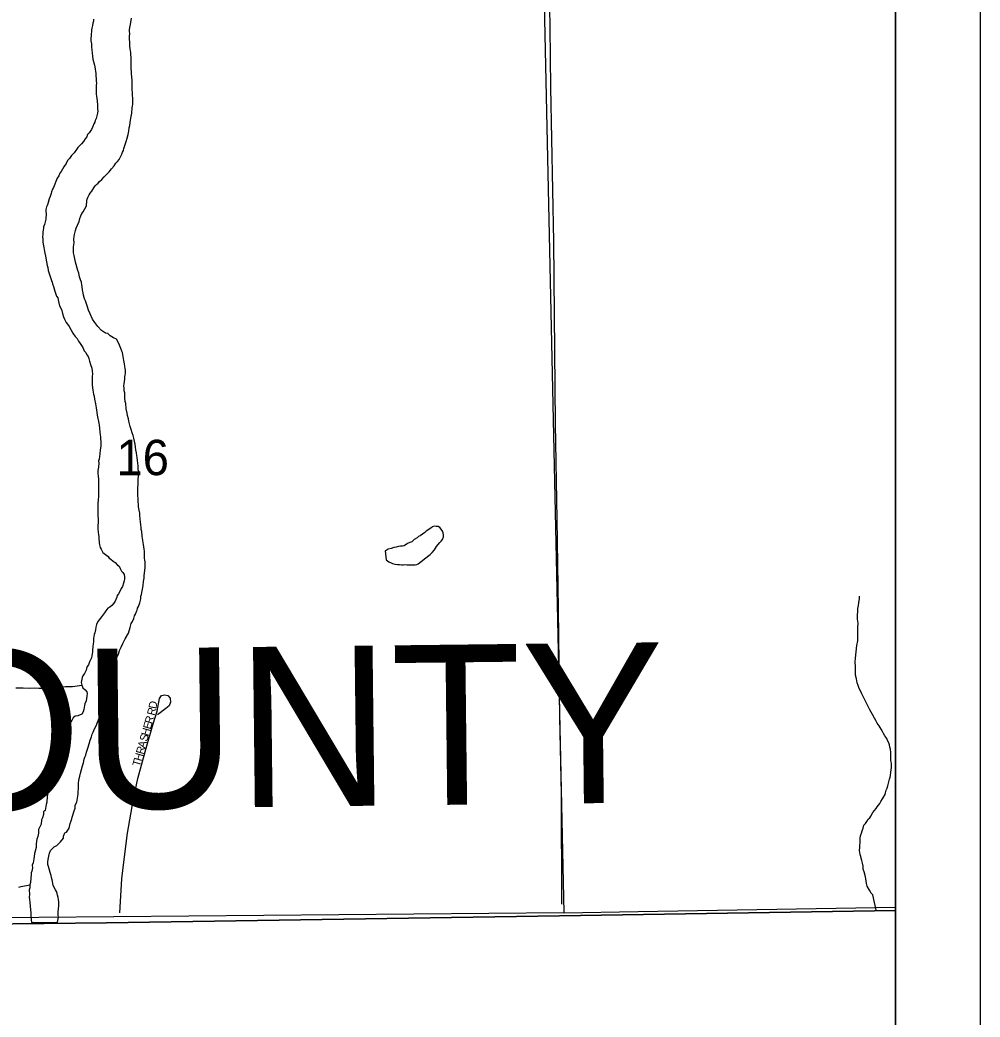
# Model space of a CAD drawing. Extents: x -10.1 to 68, y -9.5 to 29.2.
# Drawn here: x 7.864 to 9, y 16.77 to 17.95 of the extents above; entities that cross this region are included whole.
import ezdxf

# ---------------------------------------------------------------- set-up
doc = ezdxf.new("R2010")
doc.units = 0
for name, color, linetype in [('GM_X_Adjacent_County', 7, 'Continuous'), ('GM_X_Adjacent_County_Text', 7, 'Continuous'), ('GM_X_Major_River', 7, 'Continuous'), ('GM_X_Minor_Lake', 7, 'Continuous'), ('GM_X_Minor_River', 7, 'Continuous'), ('GM_X_Section', 7, 'Continuous'), ('GM_X_Section_Text', 7, 'Continuous'), ('GM_X_Township', 7, 'Continuous'), ('GM_X_Township_Road', 7, 'Continuous'), ('GM_X_Township_Subdivision', 7, 'Continuous'), ('GM_X_Township_Subdivision_Text', 7, 'Continuous'), ('SH_Data', 7, 'Continuous')]:
    doc.layers.add(name, color=color, linetype=linetype)

msp = doc.modelspace()

# ---------------------------------------------------------------- linework, layer by layer
at = {"layer": 'GM_X_Adjacent_County'}
for points in [[(2.1, 16.7954), (2.1, 14.1), (8.9, 14.1), (8.9, 16.8967)], [(8.9, 16.8967), (8.5023, 16.8904), (7.9665, 16.8821), (7.5233, 16.8774), (6.5083, 16.8667), (6.2435, 16.8638), (4.8206, 16.8372), (4.1632, 16.8285), (3.6875, 16.8223), (2.8045, 16.808), (2.1, 16.7954)]]:
    msp.add_lwpolyline(points, dxfattribs=at)
at = {"layer": 'GM_X_Major_River'}
msp.add_line((7.8774, 16.8822), (7.9083, 16.8826), dxfattribs=at)
for points in [[(7.9511, 17.951), (7.9508, 17.9484), (7.9501, 17.9461), (7.9498, 17.9434), (7.9491, 17.9403), (7.9484, 17.9384), (7.9484, 17.9358), (7.9481, 17.9335), (7.9482, 17.9316), (7.9479, 17.9281), (7.9479, 17.9251), (7.9484, 17.9217), (7.9485, 17.9182), (7.9489, 17.9141), (7.9494, 17.911), (7.9499, 17.9072), (7.9503, 17.9035), (7.952, 17.8966), (7.9524, 17.8947), (7.9529, 17.8917), (7.9533, 17.8894), (7.9537, 17.8868), (7.9538, 17.8837), (7.9543, 17.8803), (7.954, 17.8777), (7.9544, 17.8754), (7.9541, 17.8723), (7.9541, 17.8693), (7.9542, 17.8662), (7.9543, 17.8624), (7.9547, 17.8598), (7.9548, 17.8571), (7.9552, 17.8545), (7.9553, 17.8526), (7.9557, 17.8507), (7.9558, 17.8476), (7.9558, 17.8446), (7.9559, 17.8423), (7.9556, 17.8396), (7.9549, 17.8366), (7.9542, 17.8335), (7.9531, 17.8312), (7.9524, 17.8289), (7.9513, 17.827), (7.9502, 17.8239), (7.9484, 17.8205), (7.9458, 17.8166), (7.944, 17.8143), (7.9429, 17.8116), (7.9411, 17.8093), (7.9392, 17.8062), (7.9366, 17.8034), (7.9344, 17.8011), (7.9325, 17.7992), (7.9307, 17.7968), (7.9281, 17.793), (7.9248, 17.7895), (7.9226, 17.786), (7.92, 17.7837), (7.9185, 17.7802), (7.9159, 17.7763), (7.9141, 17.7733), (7.9126, 17.7709), (7.9112, 17.7686), (7.9101, 17.7656)], [(7.937, 17.7209), (7.9388, 17.7232), (7.9425, 17.7301), (7.9431, 17.7359), (7.9435, 17.7378), (7.9442, 17.7401), (7.946, 17.7432), (7.9471, 17.7451), (7.9489, 17.7474), (7.9515, 17.7513), (7.953, 17.7536), (7.9545, 17.7555), (7.9563, 17.7571), (7.9582, 17.759), (7.9608, 17.7614), (7.9634, 17.7645), (7.966, 17.7668), (7.9693, 17.7703), (7.9723, 17.7738), (7.9753, 17.7773), (7.9775, 17.7804), (7.9793, 17.7827), (7.9812, 17.785), (7.983, 17.7881), (7.9845, 17.7912), (7.9852, 17.7935), (7.9863, 17.7954), (7.987, 17.7981), (7.9895, 17.8062), (7.9909, 17.81), (7.9919, 17.8146), (7.9926, 17.8184), (7.9933, 17.8222), (7.994, 17.8253), (7.9943, 17.8287), (7.9953, 17.8337), (7.9963, 17.8398), (7.9969, 17.8459), (7.9972, 17.8482), (7.9976, 17.8505), (7.9975, 17.8539), (7.9974, 17.8558), (7.9974, 17.8577), (7.9973, 17.8604), (7.9973, 17.8638), (7.9968, 17.8676), (7.9967, 17.8706), (7.9966, 17.8748), (7.9966, 17.8782), (7.9965, 17.8828), (7.996, 17.8862), (7.9959, 17.8893), (7.9955, 17.8912), (7.9954, 17.8934), (7.9954, 17.8961), (7.9957, 17.8999), (7.9956, 17.9026), (7.9955, 17.9056), (7.9951, 17.909), (7.995, 17.9117), (7.9946, 17.9136), (7.9942, 17.9159), (7.9941, 17.9193), (7.994, 17.9235), (7.9935, 17.9276), (7.9935, 17.9303), (7.9938, 17.9341), (7.9937, 17.9364), (7.9937, 17.9383), (7.994, 17.941), (7.9947, 17.9448), (7.996, 17.9521)], [(7.9101, 17.7656), (7.9079, 17.7628), (7.9036, 17.7517), (7.9025, 17.7498), (7.9014, 17.7467), (7.9007, 17.7448), (7.8996, 17.741), (7.8985, 17.7383), (7.8975, 17.7341), (7.8964, 17.7314), (7.8953, 17.7291), (7.8946, 17.7256), (7.8947, 17.723), (7.8948, 17.7211), (7.8945, 17.7142), (7.8928, 17.7081), (7.8917, 17.7054), (7.8917, 17.7035), (7.8914, 17.7012), (7.8911, 17.6993), (7.8911, 17.6966), (7.8908, 17.6936), (7.8909, 17.6905), (7.891, 17.6875), (7.8914, 17.6848), (7.8922, 17.681), (7.8931, 17.6761), (7.8935, 17.6742), (7.894, 17.6704), (7.8953, 17.664), (7.8962, 17.6594), (7.897, 17.6572), (7.8974, 17.6538), (7.9011, 17.6417), (7.9019, 17.6398), (7.9024, 17.6379), (7.9036, 17.6345), (7.9052, 17.6292), (7.9073, 17.6232), (7.9088, 17.6213), (7.9097, 17.6171), (7.9109, 17.6118), (7.9126, 17.6081), (7.9134, 17.6062), (7.9142, 17.6028), (7.9154, 17.599), (7.9166, 17.596), (7.9186, 17.5922), (7.9202, 17.59), (7.9222, 17.5874), (7.9241, 17.584), (7.9265, 17.5795), (7.9293, 17.5757), (7.9316, 17.5731), (7.9332, 17.5701), (7.9352, 17.5671), (7.9383, 17.5626), (7.9399, 17.5585), (7.9419, 17.5566), (7.9431, 17.554), (7.9447, 17.5517), (7.9455, 17.5495), (7.9463, 17.5464), (7.9475, 17.5423), (7.9488, 17.5381), (7.9492, 17.5347), (7.9497, 17.5313), (7.9494, 17.5282), (7.9494, 17.526), (7.9495, 17.5229), (7.9492, 17.518), (7.9501, 17.5119), (7.951, 17.5073), (7.9518, 17.5051), (7.9523, 17.5013), (7.9532, 17.496), (7.954, 17.4911), (7.9549, 17.4861), (7.9554, 17.4823), (7.9571, 17.4729), (7.9576, 17.4706), (7.958, 17.4672), (7.9585, 17.4622), (7.959, 17.4592), (7.9594, 17.4569), (7.9594, 17.4543), (7.9595, 17.4508), (7.9596, 17.4459), (7.959, 17.4413), (7.9583, 17.4367), (7.9577, 17.4303), (7.957, 17.4283), (7.9571, 17.4257), (7.9568, 17.4211), (7.9561, 17.4169), (7.9562, 17.4135), (7.9566, 17.4104), (7.9567, 17.4066), (7.9568, 17.4032), (7.9569, 17.3998), (7.957, 17.3948)], [(8.0051, 17.3701), (8.0043, 17.3742), (8.0042, 17.3769), (8.0038, 17.3799), (8.0037, 17.383), (8.0036, 17.3879), (8.0035, 17.3906), (8.0035, 17.3929), (8.0034, 17.3974), (8.0037, 17.4001), (8.004, 17.4035), (8.0039, 17.4073), (8.0042, 17.41), (8.0045, 17.4157), (8.004, 17.418), (8.004, 17.4203), (8.0039, 17.4226), (8.0035, 17.4256), (8.003, 17.429), (8.0026, 17.4324), (8.0021, 17.4347), (8.002, 17.4381), (8.0012, 17.4415), (8.0008, 17.4446), (8.0003, 17.4483), (7.9995, 17.4517), (7.9986, 17.4552), (7.9978, 17.4586), (7.9966, 17.4616), (7.9957, 17.4657), (7.9945, 17.4691), (7.9937, 17.4722), (7.9928, 17.4752), (7.9924, 17.4782), (7.9912, 17.482), (7.9907, 17.485), (7.9898, 17.49), (7.9893, 17.4964), (7.9885, 17.4987), (7.988, 17.5029), (7.9879, 17.5089), (7.9874, 17.5112), (7.9874, 17.5146), (7.9869, 17.5173), (7.9873, 17.5196), (7.9879, 17.5249), (7.9882, 17.528), (7.9885, 17.5299), (7.9889, 17.5322), (7.9888, 17.5356), (7.9884, 17.5375), (7.9879, 17.5401), (7.9875, 17.5432), (7.9874, 17.5451), (7.987, 17.547), (7.9853, 17.5565), (7.9845, 17.5583), (7.9833, 17.5614), (7.9816, 17.5651), (7.9796, 17.5696), (7.9781, 17.5723), (7.9746, 17.5741), (7.9707, 17.5763), (7.968, 17.5789), (7.9653, 17.5796), (7.9603, 17.5825), (7.956, 17.5874), (7.9525, 17.5922), (7.9497, 17.596), (7.9469, 17.6024), (7.9449, 17.6065), (7.9433, 17.6118), (7.9416, 17.6179), (7.9404, 17.6201), (7.9392, 17.6243), (7.9387, 17.6273), (7.9379, 17.6303), (7.9374, 17.6345), (7.937, 17.6368), (7.9366, 17.6398), (7.9357, 17.6425), (7.9345, 17.6462), (7.9337, 17.6504), (7.9324, 17.6538), (7.9295, 17.6636), (7.9287, 17.6674), (7.9279, 17.6712), (7.9274, 17.6746), (7.9273, 17.6788), (7.9272, 17.6815), (7.9279, 17.6864), (7.9278, 17.6906), (7.9281, 17.6937), (7.9284, 17.6963), (7.9295, 17.7009), (7.9305, 17.7036), (7.932, 17.7071), (7.9338, 17.7117), (7.9348, 17.7151), (7.9359, 17.7182), (7.937, 17.7209)], [(7.957, 17.3948), (7.9567, 17.3903), (7.9568, 17.3865), (7.9565, 17.3819), (7.9562, 17.3785), (7.956, 17.3739), (7.956, 17.3705), (7.9561, 17.3678), (7.9562, 17.364), (7.9563, 17.3591), (7.9564, 17.3549), (7.9561, 17.3526), (7.9562, 17.348), (7.9563, 17.3442), (7.9567, 17.3408), (7.9571, 17.3389), (7.9572, 17.337), (7.9577, 17.3317), (7.9581, 17.329), (7.959, 17.326), (7.9601, 17.3238), (7.9621, 17.32), (7.9683, 17.3152), (7.9695, 17.3133), (7.9714, 17.3122), (7.9742, 17.3096), (7.9765, 17.3082), (7.9792, 17.3052), (7.9815, 17.3037), (7.9824, 17.3011), (7.9839, 17.2981), (7.9855, 17.2962), (7.9871, 17.2939), (7.9875, 17.2913), (7.9876, 17.289), (7.9872, 17.2867), (7.9866, 17.2836), (7.9851, 17.2798), (7.9837, 17.2775), (7.9822, 17.2737), (7.9804, 17.2713), (7.9789, 17.269), (7.9786, 17.2671), (7.9764, 17.2625), (7.9749, 17.2602), (7.9727, 17.2575), (7.9701, 17.2555), (7.9678, 17.2543), (7.9656, 17.2512), (7.9638, 17.2485), (7.9605, 17.2439), (7.9575, 17.2404), (7.956, 17.2384), (7.9546, 17.235), (7.9539, 17.2319), (7.9532, 17.2285), (7.9525, 17.225), (7.9518, 17.2231), (7.9515, 17.2208), (7.9511, 17.2182), (7.9508, 17.2147), (7.9505, 17.2117), (7.9502, 17.2094), (7.9502, 17.2075), (7.9499, 17.2056), (7.9496, 17.2025), (7.9489, 17.1979), (7.9486, 17.1953), (7.9464, 17.1907), (7.945, 17.1872), (7.9435, 17.1853), (7.9428, 17.183), (7.9421, 17.181), (7.9403, 17.1768), (7.9385, 17.1741), (7.9374, 17.1722), (7.9367, 17.1684), (7.9364, 17.1661), (7.9372, 17.163), (7.9384, 17.16), (7.9411, 17.1574), (7.9431, 17.1552), (7.9435, 17.1533), (7.9432, 17.1499), (7.9422, 17.1445), (7.9407, 17.1411), (7.9404, 17.1391), (7.9394, 17.1342), (7.9387, 17.1315), (7.9372, 17.1288), (7.9323, 17.1268), (7.9293, 17.1263), (7.9267, 17.1244), (7.9252, 17.1213), (7.9222, 17.1174), (7.92, 17.1159), (7.9171, 17.1112), (7.9153, 17.1066), (7.9142, 17.1035), (7.9128, 17.1001), (7.9117, 17.0974)], [(7.9259, 17.0068), (7.927, 17.0106), (7.9277, 17.0133), (7.9291, 17.0175), (7.9294, 17.0213), (7.9312, 17.0248), (7.9329, 17.0343), (7.9331, 17.0435), (7.9334, 17.0458), (7.9334, 17.0477), (7.9337, 17.05), (7.934, 17.0526), (7.9347, 17.0553), (7.9354, 17.0591), (7.9368, 17.0633), (7.9378, 17.0676), (7.9393, 17.0714), (7.9399, 17.0756), (7.9407, 17.0779), (7.9417, 17.0802), (7.9428, 17.084), (7.9442, 17.0886), (7.946, 17.0936), (7.947, 17.0982), (7.9485, 17.102), (7.9492, 17.1051), (7.9506, 17.1074), (7.9521, 17.1116), (7.9543, 17.1151), (7.9561, 17.1201), (7.9575, 17.1239), (7.9589, 17.1274), (7.96, 17.1316), (7.961, 17.1347), (7.9617, 17.1373), (7.9624, 17.14), (7.9635, 17.1431), (7.9646, 17.1473), (7.9695, 17.1634), (7.971, 17.1672), (7.972, 17.1707), (7.9723, 17.1737), (7.9734, 17.1757), (7.9748, 17.1806), (7.9758, 17.1879), (7.9761, 17.1898), (7.9768, 17.1925), (7.9787, 17.1963), (7.9805, 17.1998), (7.9819, 17.204), (7.9837, 17.2082), (7.9855, 17.2125), (7.9884, 17.2179), (7.9925, 17.2248), (7.9942, 17.2313), (7.9956, 17.2359), (7.9971, 17.2386), (7.9985, 17.2421), (7.9996, 17.2451), (8.0007, 17.2471), (8.0018, 17.2501), (8.0025, 17.252), (8.0032, 17.254), (8.0043, 17.2563), (8.0057, 17.2605), (8.0068, 17.2651), (8.0071, 17.2685), (8.0078, 17.2704), (8.0098, 17.2811), (8.0101, 17.2857), (8.0108, 17.2895), (8.0111, 17.293), (8.0114, 17.2956), (8.0117, 17.2991), (8.012, 17.3017), (8.012, 17.304), (8.0119, 17.3063), (8.0119, 17.3086), (8.0118, 17.3112), (8.0114, 17.3131), (8.0113, 17.3158), (8.0113, 17.3185), (8.0112, 17.3215), (8.0108, 17.3238), (8.0107, 17.3268), (8.0102, 17.3295), (8.0098, 17.3317), (8.0094, 17.3344), (8.0089, 17.3371), (8.0085, 17.3393), (8.0085, 17.3412), (8.008, 17.3431), (8.008, 17.345), (8.0075, 17.3473), (8.0075, 17.3492), (8.007, 17.353), (8.0066, 17.356), (8.0061, 17.3598), (8.0057, 17.3636), (8.0056, 17.3667), (8.0051, 17.3701)], [(7.9117, 17.0974), (7.9106, 17.0943), (7.9095, 17.0913), (7.9085, 17.0871), (7.9071, 17.0809), (7.9042, 17.0759), (7.9031, 17.074), (7.9027, 17.0721), (7.902, 17.0694), (7.9013, 17.0663), (7.901, 17.0641), (7.9004, 17.0595), (7.9001, 17.0545), (7.8994, 17.0518), (7.8991, 17.0484), (7.8988, 17.0454), (7.8974, 17.0385), (7.8963, 17.0358), (7.8964, 17.0335), (7.8961, 17.0312), (7.8958, 17.0247), (7.8948, 17.0221), (7.8938, 17.0148), (7.8919, 17.0132), (7.8916, 17.0102), (7.8906, 17.006), (7.8895, 17.0037), (7.8892, 16.9987), (7.8859, 16.9922), (7.886, 16.988), (7.885, 16.9842), (7.8839, 16.9811), (7.8836, 16.978), (7.8833, 16.9754), (7.883, 16.9712), (7.8819, 16.9666), (7.8812, 16.9639), (7.8806, 16.9605), (7.8802, 16.9578), (7.8796, 16.9528), (7.8785, 16.9501), (7.8786, 16.9471), (7.8779, 16.9429), (7.8772, 16.941), (7.8772, 16.9391), (7.877, 16.9349), (7.8763, 16.9295), (7.8756, 16.9269), (7.8757, 16.9234), (7.875, 16.9208), (7.8751, 16.9154), (7.8748, 16.9124), (7.8753, 16.9094), (7.8757, 16.9063), (7.8762, 16.9014), (7.8768, 16.8938), (7.8768, 16.89), (7.8774, 16.8822)], [(7.9083, 16.8826), (7.9096, 16.8888), (7.9092, 16.8911), (7.9091, 16.8934), (7.9091, 16.8953), (7.9094, 16.898), (7.91, 16.9025), (7.9099, 16.9067), (7.9095, 16.9094), (7.9091, 16.912), (7.9082, 16.9147), (7.9078, 16.9166), (7.907, 16.9192), (7.9058, 16.9211), (7.9046, 16.9237), (7.9034, 16.9267), (7.903, 16.9286), (7.9025, 16.9309), (7.9021, 16.9328), (7.9013, 16.9354), (7.9009, 16.9381), (7.8996, 16.9415), (7.8984, 16.9457), (7.8976, 16.9487), (7.8971, 16.951), (7.8971, 16.954), (7.8974, 16.9567), (7.8981, 16.9609), (7.8987, 16.9643), (7.9002, 16.9674), (7.902, 16.9693), (7.9043, 16.9717), (7.9077, 16.9736), (7.9121, 16.9779), (7.9154, 16.9822), (7.9154, 16.9845), (7.9172, 16.9883), (7.9191, 16.9891), (7.922, 16.9941), (7.9234, 16.9995), (7.9245, 17.0026), (7.9252, 17.0049), (7.9259, 17.0068)]]:
    msp.add_lwpolyline(points, dxfattribs=at)
at = {"layer": 'GM_X_Minor_Lake'}
for points in [[(8.3478, 17.3163), (8.3492, 17.3178), (8.3518, 17.3201), (8.3544, 17.3232), (8.3569, 17.3271), (8.3584, 17.329), (8.3606, 17.3317), (8.3625, 17.3333), (8.364, 17.3356), (8.365, 17.3387), (8.365, 17.3406), (8.3649, 17.3432), (8.3641, 17.3451), (8.3622, 17.3477), (8.3606, 17.3496), (8.3587, 17.3507), (8.3564, 17.3506), (8.3541, 17.351), (8.3522, 17.3502), (8.3503, 17.349), (8.3447, 17.3451), (8.3429, 17.3435), (8.3402, 17.3419), (8.3376, 17.3399), (8.3357, 17.3388), (8.3339, 17.3372), (8.3305, 17.3356), (8.3275, 17.3325), (8.3252, 17.3317), (8.3226, 17.3305), (8.3185, 17.3281), (8.3166, 17.3277), (8.3143, 17.3276), (8.312, 17.3272), (8.309, 17.3264), (8.3064, 17.3259), (8.303, 17.3247), (8.2995, 17.3239), (8.2973, 17.3223), (8.2962, 17.3219)], [(8.2962, 17.3219), (8.2972, 17.3112), (8.3003, 17.309), (8.303, 17.308), (8.3049, 17.3069), (8.3076, 17.3062), (8.3106, 17.3058), (8.3129, 17.3059), (8.3156, 17.3056), (8.3175, 17.3056), (8.3194, 17.3057), (8.3217, 17.3053), (8.3243, 17.3054), (8.3281, 17.3055), (8.3315, 17.3056), (8.3334, 17.306), (8.3353, 17.3068), (8.3478, 17.3163)]]:
    msp.add_lwpolyline(points, dxfattribs=at)
at = {"layer": 'GM_X_Minor_River'}
for points in [[(8.8553, 17.2314), (8.8556, 17.2364), (8.8551, 17.2413), (8.855, 17.2459), (8.8552, 17.2501), (8.8555, 17.2539), (8.8562, 17.2573), (8.8565, 17.2604), (8.8568, 17.2634), (8.8572, 17.2654), (8.8575, 17.2673), (8.8575, 17.2684)], [(8.877, 16.8968), (8.8732, 16.9149), (8.8712, 16.9171), (8.8692, 16.9205), (8.8665, 16.9254), (8.8656, 16.9284), (8.8652, 16.9314), (8.8647, 16.9341), (8.8643, 16.9364), (8.8627, 16.9424), (8.8618, 16.9454), (8.8617, 16.9489), (8.8609, 16.9527), (8.8601, 16.9557), (8.8592, 16.9583), (8.8588, 16.9606), (8.858, 16.9629), (8.8576, 16.9651), (8.8575, 16.9674), (8.8578, 16.9712), (8.8578, 16.9735), (8.8581, 16.9766), (8.858, 16.9796), (8.8583, 16.9823), (8.8586, 16.9849), (8.8597, 16.988), (8.8604, 16.9907), (8.8615, 16.9941), (8.8625, 16.9976), (8.8644, 16.9995), (8.8659, 17.0019), (8.8677, 17.0046), (8.8696, 17.0061), (8.8707, 17.0081), (8.8732, 17.0123), (8.8751, 17.015), (8.8769, 17.0173), (8.8784, 17.0193), (8.8799, 17.0212), (8.8814, 17.0231), (8.8824, 17.0254), (8.8847, 17.0285), (8.8857, 17.0308), (8.8876, 17.0339), (8.8883, 17.0358), (8.889, 17.0389), (8.8901, 17.0412), (8.8908, 17.0439), (8.8929, 17.0519), (8.8936, 17.0542), (8.8939, 17.0561), (8.8946, 17.0603), (8.8949, 17.063), (8.8952, 17.0657), (8.8952, 17.068), (8.8951, 17.071), (8.8946, 17.074), (8.8946, 17.0778), (8.8945, 17.0805), (8.8944, 17.0836), (8.894, 17.0873), (8.8932, 17.0896), (8.8927, 17.0926), (8.8919, 17.0949), (8.8903, 17.0975), (8.8895, 17.1002), (8.8875, 17.1032), (8.8859, 17.1058), (8.8844, 17.1084), (8.8831, 17.1111), (8.8816, 17.1129), (8.8808, 17.1148), (8.8784, 17.1182), (8.8768, 17.1212), (8.8749, 17.1242), (8.8729, 17.1283), (8.8697, 17.134), (8.8673, 17.1385), (8.8653, 17.1426), (8.8633, 17.1464), (8.8621, 17.149), (8.8609, 17.1513), (8.8597, 17.1535), (8.8585, 17.1562), (8.8569, 17.1592), (8.8557, 17.1626), (8.8545, 17.166), (8.8536, 17.1705), (8.8528, 17.1751), (8.8527, 17.1796), (8.8525, 17.185), (8.8524, 17.1903), (8.8527, 17.1952), (8.8543, 17.2101), (8.8553, 17.2155), (8.8555, 17.2212), (8.8554, 17.2257), (8.8553, 17.2314)], [(7.8589, 17.1601), (7.8676, 17.1599), (7.8749, 17.1597), (7.8809, 17.1599), (7.8863, 17.1596), (7.8912, 17.1597), (7.8965, 17.1602), (7.9121, 17.1613), (7.9178, 17.1615), (7.9216, 17.1616), (7.9239, 17.1616), (7.9258, 17.1616), (7.9262, 17.1617), (7.9372, 17.163)], [(7.8627, 16.9243), (7.8654, 16.9251), (7.8654, 16.9251), (7.8756, 16.9269)]]:
    msp.add_lwpolyline(points, dxfattribs=at)
at = {"layer": 'GM_X_Section'}
msp.add_line((8.9, 16.9006), (8.9, 18.0173), dxfattribs=at)
msp.add_lwpolyline([(8.9, 18.0173), (8.4834, 18.0059), (8.5076, 16.8938), (8.5955, 16.8955), (8.9, 16.9006)], dxfattribs=at)
msp.add_lwpolyline([(8.4834, 18.0059), (8.5076, 16.8938), (7.6195, 16.8859), (7.5357, 16.8848), (7.5119, 17.9844)], close=True, dxfattribs=at)
at = {"layer": 'GM_X_Township'}
for points in [[(8.9, 16.8967), (8.9, 20.9), (6.49, 20.9)], [(6.49, 20.9), (6.4976, 19.3842), (6.5141, 17.4202), (6.5083, 16.8667), (7.5233, 16.8774), (7.9665, 16.8821), (8.5023, 16.8904), (8.9, 16.8967)]]:
    msp.add_lwpolyline(points, dxfattribs=at)
at = {"layer": 'GM_X_Township_Road'}
msp.add_lwpolyline([(8.491, 18.7), (8.486, 18.6991), (8.4829, 18.6965), (8.4807, 18.6936), (8.4797, 18.6906), (8.4789, 18.6859), (8.4797, 18.6483), (8.4814, 18.513), (8.485, 18.2926), (8.4868, 18.2018), (8.4884, 18.0835), (8.4908, 17.9409), (8.4916, 17.8702), (8.4953, 17.6878), (8.4974, 17.4724), (8.4993, 17.3594), (8.5006, 17.253), (8.5022, 17.1249), (8.5043, 17.0341), (8.5049, 16.904)], dxfattribs=at)
at = {"layer": 'GM_X_Township_Subdivision'}
msp.add_lwpolyline([(7.982, 16.8937), (7.9845, 16.9339), (7.9867, 16.9536), (7.9911, 16.9879), (7.998, 17.0264), (8.0036, 17.0526), (8.0132, 17.0884), (8.0215, 17.1173), (8.0264, 17.1323), (8.0291, 17.1472), (8.0315, 17.1509), (8.0352, 17.1517), (8.0391, 17.1509), (8.0416, 17.1477), (8.0421, 17.1431), (8.0406, 17.1387), (8.0365, 17.1355), (8.0266, 17.1279)], dxfattribs=at)
at = {"layer": 'SH_Data'}
for p, q in [((9, 21), (9, 14)), ((8.9, 20.9), (8.9, 14.1))]:
    msp.add_line(p, q, dxfattribs=at)

# ---------------------------------------------------------------- texts
at = {"layer": 'GM_X_Adjacent_County_Text'}
msp.add_text('GEAUGA COUNTY', height=0.189394, rotation=0.6619, dxfattribs=at).set_placement((6.4044, 16.9988))
at = {"layer": 'GM_X_Section_Text'}
msp.add_text('16', height=0.04186, rotation=0, dxfattribs=at).set_placement((7.978, 17.4115))
at = {"layer": 'GM_X_Township_Subdivision_Text'}
for s, rotation, p in [('D', 79.9551, (8.0252, 17.1345)), ('R', 73.9784, (8.0203, 17.1166)), ('R', 75.6012, (8.0232, 17.1265)), ('E', 73.9758, (8.0185, 17.1102)), ('S', 73.975, (8.0143, 17.0958)), ('H', 73.9957, (8.0162, 17.1022)), ('A', 73.9706, (8.012, 17.0878)), ('H', 73.982, (8.0077, 17.0725)), ('R', 73.9845, (8.01, 17.0806)), ('T', 73.9758, (8.0058, 17.0661))]:
    msp.add_text(s, height=0.00947, rotation=rotation, dxfattribs=at).set_placement(p)

doc.saveas('drawing.dxf')
